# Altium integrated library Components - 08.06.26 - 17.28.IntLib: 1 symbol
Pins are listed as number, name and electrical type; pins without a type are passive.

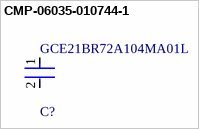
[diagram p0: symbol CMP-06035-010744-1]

## CMP-06035-010744-1
designator C?, comment GCE21BR72A104MA01L
Ceramic Capacitor 100nF ±20% 100V X7R 0805
footprint FP-GCE21B-0_3-IPC_C
footprint FP-GCE21B-0_3-MFG
footprint FP-GCE21B-0_3-IPC_B
footprint FP-GCE21B-0_3-IPC_A
pins: 1, 2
